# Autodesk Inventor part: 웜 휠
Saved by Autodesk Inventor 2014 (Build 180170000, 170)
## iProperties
Created: 2026-07
Part Number: 웜 휠
Material: 일반
Document SubType Name: Modeling
Designer: dg
Density: 1 g/cm^3
Appearance: 기본값
Author: dg
Author: jhkim
Creation Date: 2026-07-02
Sending System: Autodesk Inventor 2027
Preprocessor: ST-DEVELOPER v20.1
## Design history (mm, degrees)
node "웜 휠1"
node "솔리드1"
node "기준1"
